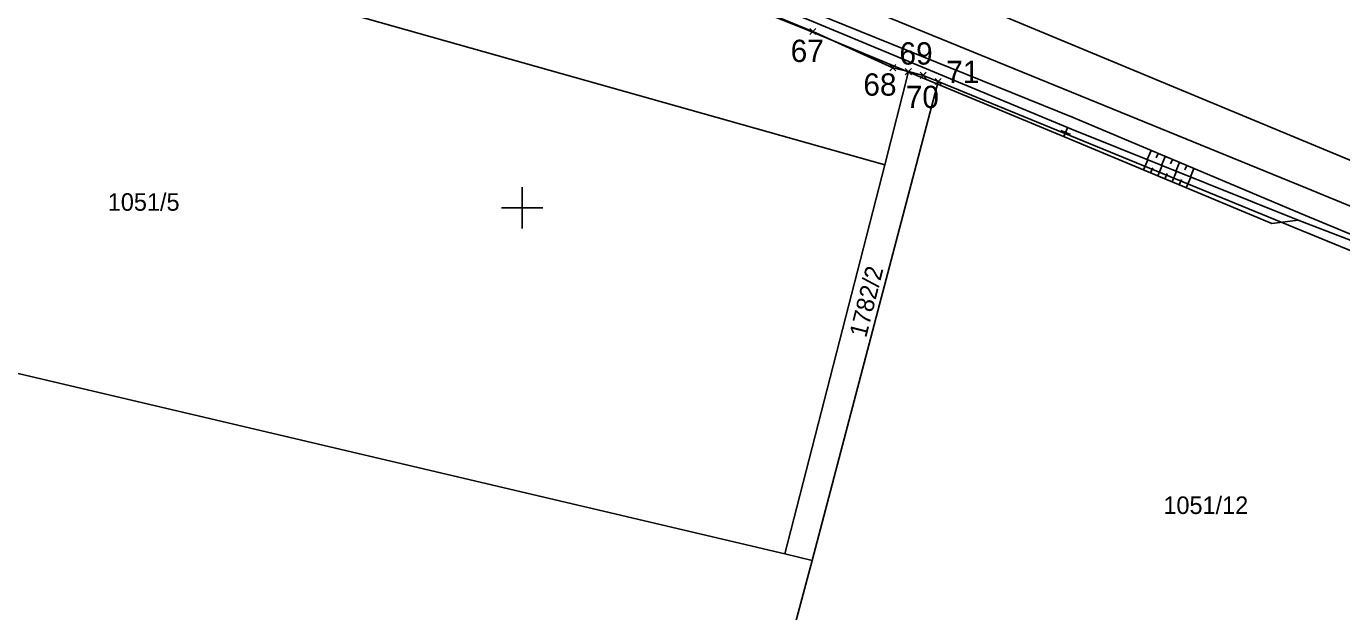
# Model space of a CAD drawing. Extents: x -779302 to -774398, y -1144902 to -1142831.
# Drawn here: x -776048 to -775920.6, y -1144339.1 to -1144282.4 of the extents above; entities that cross this region are included whole.
import ezdxf

# ---------------------------------------------------------------- set-up
doc = ezdxf.new("R2010")
doc.units = 0
for name, color, linetype in [('hektosit - Vrstva 5', 7, 'Continuous'), ('Hranice parcel', 7, 'Continuous'), ('legenda I_5_2 - Vrstva 53', 7, 'Continuous'), ('Parcelní čísla', 7, 'Continuous'), ('SŽDC', 7, 'Continuous'), ('zjednodus_g_situ-seda - Vrstva 1', 7, 'Continuous'), ('zjednodus_g_situ-seda - Vrstva 48', 7, 'Continuous'), ('zjednodus_g_situ-seda - Vrstva 49', 7, 'Continuous'), ('zjednodus_g_situ-seda - Vrstva 7', 7, 'Continuous')]:
    doc.layers.add(name, color=color, linetype=linetype)

msp = doc.modelspace()

# ---------------------------------------------------------------- linework, layer by layer
at = {"layer": 'hektosit - Vrstva 5'}
for p, q in [((-776000, -1144298), (-776000, -1144302)), ((-776002, -1144300), (-775998, -1144300))]:
    msp.add_line(p, q, dxfattribs=at)
at = {"layer": 'Hranice parcel'}
for p, q in [((-775964.86, -1144295.82), (-776100.36, -1144257.59)), ((-775964.86, -1144295.82), (-775962.59, -1144286.8)), ((-775959.71, -1144287.76), (-775971.9, -1144334.14)), ((-775974.56, -1144333.51), (-775964.86, -1144295.82)), ((-775974.56, -1144333.51), (-776104.65, -1144302.9)), ((-775981.59, -1144370.37), (-775971.9, -1144334.14)), ((-775971.9, -1144334.14), (-775974.56, -1144333.51))]:
    msp.add_line(p, q, dxfattribs=at)
for points in [[(-776082.64, -1144237.51), (-776064.26, -1144245.03), (-775971.84, -1144282.92), (-775964.09, -1144286.42), (-775962.59, -1144286.8)], [(-775863.23, -1144318.85), (-775876.16, -1144313.52), (-775955.63, -1144280.49)], [(-775962.59, -1144286.8), (-775961.16, -1144287.17), (-775959.71, -1144287.76)], [(-775959.71, -1144287.76), (-775879.1, -1144320.81), (-775872.73, -1144323.39)]]:
    msp.add_lwpolyline(points, dxfattribs=at)
at = {"layer": 'legenda I_5_2 - Vrstva 53'}
for points in [[(-776052.08, -1144238.11), (-776022.68, -1144250.27), (-776023.78, -1144252.86), (-775962.18, -1144277.9), (-775959.79, -1144278.81), (-775958.42, -1144279.33), (-775955.63, -1144280.49), (-775876.16, -1144313.52), (-775863.23, -1144318.85), (-775854.19, -1144322.57), (-775848.16, -1144325.04), (-775838.53, -1144328.62), (-775690.5, -1144389.48), (-775626.91, -1144413.11), (-775574.03, -1144428.55), (-775529.11, -1144439.07), (-775474.88, -1144449.28), (-775426.17, -1144455.72)], [(-775655.04, -1144411.89), (-775699.86, -1144394.42), (-775786.82, -1144358.72), (-775824.31, -1144343.39), (-775839.31, -1144337.25), (-775851.34, -1144332.37), (-775858.65, -1144329.3), (-775860.54, -1144328.51), (-775865.63, -1144326.37), (-775872.73, -1144323.39), (-775879.1, -1144320.81), (-775959.71, -1144287.76), (-775961.16, -1144287.17), (-775962.59, -1144286.8), (-775964.09, -1144286.42), (-775971.84, -1144282.92), (-776064.26, -1144245.03)]]:
    msp.add_lwpolyline(points, dxfattribs=at)
at = {"layer": 'SŽDC'}
for p, q in [((-775971.64, -1144283.12), (-775972.14, -1144282.62)), ((-775971.64, -1144282.72), (-775972.14, -1144283.22)), ((-775972.04, -1144283.12), (-775971.54, -1144282.62)), ((-775972.04, -1144282.72), (-775971.54, -1144283.22)), ((-775971.84, -1144282.92), (-775971.84, -1144282.92)), ((-775963.89, -1144286.62), (-775964.39, -1144286.12)), ((-775963.89, -1144286.22), (-775964.39, -1144286.72)), ((-775964.29, -1144286.62), (-775963.79, -1144286.12)), ((-775964.29, -1144286.22), (-775963.79, -1144286.72)), ((-775964.09, -1144286.42), (-775964.09, -1144286.42)), ((-775962.39, -1144287), (-775962.89, -1144286.5)), ((-775962.39, -1144286.6), (-775962.89, -1144287.1)), ((-775962.79, -1144287), (-775962.29, -1144286.5)), ((-775962.79, -1144286.6), (-775962.29, -1144287.1)), ((-775962.59, -1144286.8), (-775962.59, -1144286.8)), ((-775960.96, -1144287.37), (-775961.46, -1144286.87)), ((-775960.96, -1144286.97), (-775961.46, -1144287.47)), ((-775961.36, -1144287.37), (-775960.86, -1144286.87)), ((-775961.36, -1144286.97), (-775960.86, -1144287.47)), ((-775961.16, -1144287.17), (-775961.16, -1144287.17)), ((-775959.51, -1144287.96), (-775960.01, -1144287.46)), ((-775959.51, -1144287.56), (-775960.01, -1144288.06)), ((-775959.91, -1144287.96), (-775959.41, -1144287.46)), ((-775959.91, -1144287.56), (-775959.41, -1144288.06)), ((-775959.71, -1144287.76), (-775959.71, -1144287.76))]:
    msp.add_line(p, q, dxfattribs=at)
for points in [[(-776052.08, -1144238.11), (-776022.68, -1144250.27), (-776023.78, -1144252.86), (-775962.18, -1144277.9), (-775959.79, -1144278.81), (-775958.42, -1144279.33), (-775955.63, -1144280.49), (-775876.16, -1144313.52), (-775863.23, -1144318.85), (-775854.19, -1144322.57), (-775848.16, -1144325.04), (-775838.53, -1144328.62), (-775690.5, -1144389.48), (-775626.91, -1144413.11), (-775574.03, -1144428.55), (-775529.11, -1144439.07), (-775474.88, -1144449.28), (-775426.17, -1144455.72)], [(-775655.04, -1144411.89), (-775699.86, -1144394.42), (-775786.82, -1144358.72), (-775824.31, -1144343.39), (-775839.31, -1144337.25), (-775851.34, -1144332.37), (-775858.65, -1144329.3), (-775860.54, -1144328.51), (-775865.63, -1144326.37), (-775872.73, -1144323.39), (-775879.1, -1144320.81), (-775959.71, -1144287.76), (-775961.16, -1144287.17), (-775962.59, -1144286.8), (-775964.09, -1144286.42), (-775971.84, -1144282.92), (-776064.26, -1144245.03)]]:
    msp.add_lwpolyline(points, dxfattribs=at)
at = {"layer": 'zjednodus_g_situ-seda - Vrstva 1'}
msp.add_lwpolyline([(-775727.95, -1144378.48), (-775748.85, -1144369.93), (-775769.93, -1144361.28), (-775794.14, -1144351.36), (-775818.2, -1144341.5), (-775834.95, -1144334.63), (-775848.54, -1144329.06), (-775863.63, -1144322.87), (-775881.7, -1144315.46), (-775900.23, -1144307.86), (-775924.1, -1144298.07), (-775945.91, -1144289.14), (-775969.09, -1144279.64), (-775991.27, -1144270.55), (-776009.96, -1144262.88), (-776026.16, -1144256.24), (-776044.9, -1144248.56), (-776062.23, -1144241.45)], dxfattribs=at)
at = {"layer": 'zjednodus_g_situ-seda - Vrstva 48'}
for p, q in [((-775939.09, -1144294.44), (-775939.46, -1144295.32)), ((-775938.4, -1144294.73), (-775938.58, -1144295.16)), ((-775939.82, -1144296.31), (-775939.41, -1144295.34)), ((-775938.43, -1144296.89), (-775938.02, -1144295.9)), ((-775937.71, -1144295.02), (-775938.07, -1144295.88)), ((-775937.02, -1144295.31), (-775937.19, -1144295.73)), ((-775936.32, -1144295.6), (-775936.67, -1144296.43)), ((-775935.63, -1144295.89), (-775935.81, -1144296.3)), ((-775939.13, -1144296.6), (-775938.92, -1144296.11)), ((-775937.74, -1144297.18), (-775937.53, -1144296.68)), ((-775937.05, -1144297.47), (-775936.62, -1144296.45)), ((-775936.36, -1144297.76), (-775936.14, -1144297.25)), ((-775935.67, -1144298.05), (-775935.23, -1144297.01)), ((-775934.94, -1144296.18), (-775935.28, -1144296.99))]:
    msp.add_line(p, q, dxfattribs=at)
at = {"layer": 'zjednodus_g_situ-seda - Vrstva 49'}
for points in [[(-775901.11, -1144310.28), (-775924.51, -1144300.58), (-775946.64, -1144291.26), (-775971.62, -1144281.13), (-775992.15, -1144272.75), (-776010.45, -1144265.24), (-776024.6, -1144259.39), (-776025.05, -1144259.34), (-776025.14, -1144259.53), (-776025.8, -1144259.23), (-776026.13, -1144259.56), (-776026.14, -1144259.55)], [(-775901.11, -1144310.28), (-775924.83, -1144301.18), (-775946.8, -1144292.38), (-775971.77, -1144281.97), (-775992.1, -1144273.72), (-776010.81, -1144266.07), (-776025.17, -1144260.46)], [(-775924.83, -1144301.18), (-775927.39, -1144301.51), (-775947.02, -1144293.3), (-775972.86, -1144282.57), (-775991.79, -1144275.01), (-776010.81, -1144266.07)]]:
    msp.add_lwpolyline(points, dxfattribs=at)
at = {"layer": 'zjednodus_g_situ-seda - Vrstva 7'}
for p, q in [((-775946.89, -1144292.89), (-775947.82, -1144292.51)), ((-775947.55, -1144293.16), (-775947.17, -1144292.24))]:
    msp.add_line(p, q, dxfattribs=at)

# ---------------------------------------------------------------- texts
at = {"layer": 'Parcelní čísla'}
for s, p in [('1051/5', (-776040.13, -1144300.28)), ('1051/12', (-775937.89, -1144329.65))]:
    msp.add_text(s, height=1.7, dxfattribs=at).set_placement(p)
msp.add_text('1782/2', height=1.7, rotation=76, dxfattribs=at).set_placement((-775966.68, -1144312.65))
at = {"layer": 'SŽDC'}
for s, p in [('67', (-775973.99, -1144285.87)), ('69', (-775963.45, -1144286.12)), ('71', (-775958.92, -1144287.91)), ('68', (-775966.95, -1144289.13)), ('70', (-775962.84, -1144290.33))]:
    msp.add_text(s, height=2.16, dxfattribs=at).set_placement(p)

doc.saveas('drawing.dxf')
